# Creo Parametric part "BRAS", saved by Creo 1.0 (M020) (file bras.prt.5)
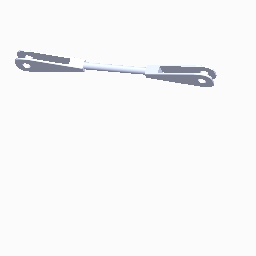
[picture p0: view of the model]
Units: millimeter Newton Second (mmNs); MM, TONNE, SECS
Materials in the file: FE20

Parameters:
  PTC_MATERIAL_NAME = "FE20"

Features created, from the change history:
  datum axis "A_1"
  datum axis "A_2" (2 times)
  datum plane "DTM1"

Other named items: BRAS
